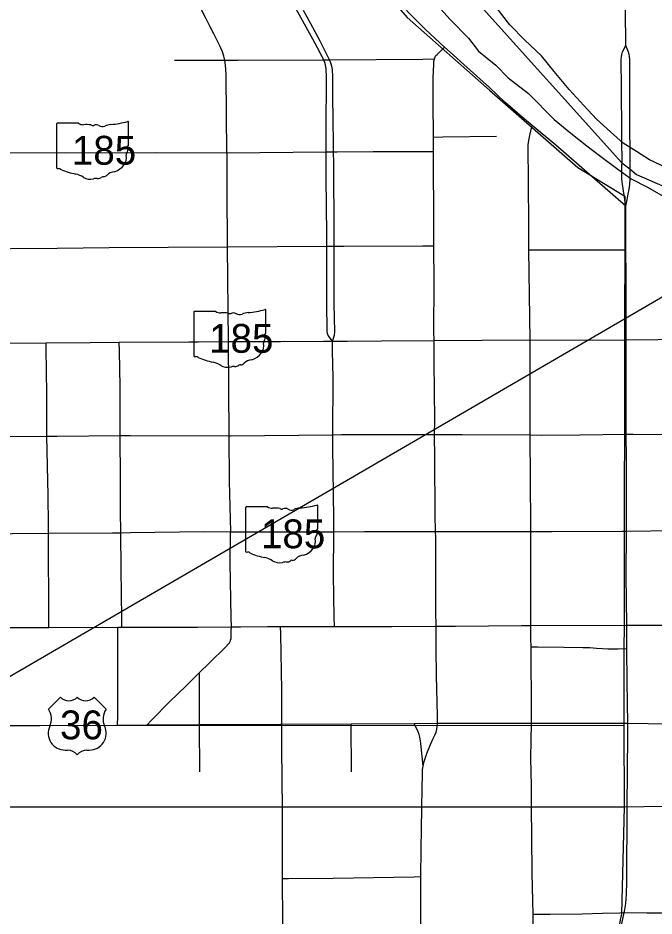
# Model space of a CAD drawing. Extents: x -87 to 2145, y -2128 to 440.
# Drawn here: x 517.5 to 594.3, y -979.3 to -870.9 of the extents above; entities that cross this region are included whole.
import ezdxf

# ---------------------------------------------------------------- set-up
doc = ezdxf.new("R2010")
doc.units = 0
for name, color, linetype in [('Default', 7, 'Continuous'), ('GM_X_City_Street', 7, 'Continuous'), ('GM_X_County_Road', 7, 'Continuous'), ('GM_X_Major_River', 7, 'Continuous'), ('GM_X_Rail_Line', 7, 'Continuous'), ('GM_X_State_Route', 7, 'Continuous'), ('GM_X_State_Shield', 7, 'Continuous'), ('GM_X_Township', 7, 'Continuous'), ('GM_X_Township_Text', 7, 'Continuous'), ('GM_X_US_Route', 7, 'Continuous'), ('GM_X_US_Shield', 7, 'Continuous'), ('SC_Scratch1', 7, 'Continuous')]:
    doc.layers.add(name, color=color, linetype=linetype)

msp = doc.modelspace()

# ---------------------------------------------------------------- linework, layer by layer
at = {"layer": 'Default'}
msp.add_circle((557.31, -928.35), 114.66, dxfattribs=at)
at = {"layer": 'GM_X_City_Street'}
msp.add_line((557.79, -961.89), (557.74, -956.06), dxfattribs=at)
for points in [[(555.49, -909.89), (554.97, -909.19), (554.89, -908.94), (554.86, -908.67), (554.85, -908.4), (554.81, -905.54), (554.82, -903.09), (554.82, -898.7), (554.82, -898.42), (554.82, -897.01), (554.75, -890.14), (554.75, -887.97), (554.75, -887.01), (554.74, -886.41), (554.75, -883.05), (554.79, -879.41), (554.79, -878.03), (554.74, -876.95), (554.67, -876.57), (554.6, -876.34), (554.46, -875.91), (554.35, -875.7), (554.21, -875.43), (554.11, -875.23), (553.7, -874.47), (553.14, -873.4), (550.86, -869.36)], [(542.73, -887.14), (542.68, -877.84), (542.64, -876.98), (542.54, -876.23), (542.49, -875.95), (542.4, -875.48), (542.21, -874.95), (541.9, -874.21), (541.55, -873.49), (541.18, -872.77), (540.73, -871.91), (540.25, -870.97), (539.65, -869.81)], [(555.49, -909.89), (555.66, -909.41), (555.74, -909.14), (555.78, -908.74), (555.71, -905.36), (555.71, -902.88), (555.69, -899.41), (555.69, -898.42), (555.7, -895.31), (555.65, -890.02), (555.65, -888.4), (555.64, -887), (555.64, -886.01), (555.56, -880.31), (555.56, -878.43), (555.55, -877.96), (555.5, -877.08), (555.43, -876.68), (555.35, -876.44), (555.27, -876.21), (555.13, -875.91), (554.98, -875.58), (554.01, -873.64), (553.15, -871.99), (552, -869.94)], [(566.31, -966.29), (566.31, -966.07), (566.36, -961.99), (566.38, -961.6), (566.44, -961.19), (566.56, -960.61), (566.88, -959.67), (567.32, -958.57), (567.61, -957.94), (567.88, -957.43), (568.02, -957.08), (568.11, -956.71), (568.2, -956.01), (568.17, -955.06), (568.06, -950.28), (568.03, -946.94), (568.01, -944.29), (567.99, -942.51), (567.99, -939.1), (567.97, -933.59), (567.96, -932.86), (567.92, -930.85), (567.87, -923.97), (567.83, -921.15), (567.85, -919.46), (567.77, -912.37), (567.76, -909.78), (567.75, -908.73), (567.76, -902.84), (567.75, -898.36), (567.74, -896.28), (567.71, -886.98), (567.7, -885.24), (567.67, -880.94), (567.67, -879.07), (567.65, -878.04), (567.68, -877.26), (567.72, -876.44), (567.75, -876.09), (567.81, -875.8), (567.9, -875.56), (568, -875.39), (568.13, -875.26), (569.03, -874.36)], [(536.44, -875.96), (542.49, -875.95), (544.11, -875.95), (554.46, -875.91), (554.84, -875.91), (555.13, -875.91)], [(555.13, -875.91), (566.4, -875.81), (567.81, -875.8)], [(579.36, -909.7), (579.21, -898.86), (579.21, -895.64), (579.14, -886.13), (579.25, -885.44), (579.36, -884.83), (579.61, -883.84)], [(567.7, -885.24), (568.84, -885.22), (575.32, -885.12)], [(542.73, -887.14), (554.75, -887.01), (555.64, -887), (556.08, -887), (560.4, -886.98), (566.46, -886.98), (567.71, -886.98)], [(447.52, -899), (448.88, -898.99), (463.39, -898.9), (473.66, -898.82), (474.44, -898.82), (485.35, -898.8), (487.31, -898.8), (495.53, -898.78), (499.39, -898.77), (502.67, -898.76), (509.93, -898.74), (510.42, -898.73), (510.99, -898.73), (522.28, -898.66), (528.55, -898.57), (542.79, -898.48), (554.82, -898.42), (555.69, -898.42), (556.86, -898.41), (566.4, -898.36), (567.75, -898.36)], [(579.21, -898.86), (580.2, -898.86), (590.94, -898.83)], [(511.1, -910.15), (520.94, -910.07), (526.26, -910.03), (529.75, -910.01), (538.14, -909.95), (539.31, -909.95), (542.91, -909.93), (549.23, -909.9), (554.42, -909.89), (555.49, -909.89), (557.26, -909.88), (561.42, -909.83), (567.76, -909.78), (579.36, -909.7)], [(521.27, -944.43), (521.26, -943.73), (521.25, -939.89), (521.21, -936.85), (521.21, -934.23), (521.2, -933.07), (521.2, -932.04), (521.17, -928.51), (521.03, -921.34), (521.01, -916.24), (520.95, -910.75), (520.94, -910.07)], [(530.09, -944.42), (530.07, -943.35), (529.97, -937.41), (529.93, -933), (529.91, -930.37), (529.9, -926.55), (529.87, -921.26), (529.87, -918.51), (529.85, -915.37), (529.77, -911.1), (529.75, -910.01)], [(555.75, -944.34), (555.72, -943.19), (555.63, -938.09), (555.67, -932.88), (555.68, -931.29), (555.58, -925.45), (555.55, -922.76), (555.56, -921.17), (555.6, -914.3), (555.52, -911.06), (555.49, -909.89)], [(516.04, -921.4), (521.03, -921.34), (522.25, -921.33), (529.87, -921.26), (531.06, -921.25), (543, -921.32), (543.17, -921.32), (555.56, -921.17), (556.6, -921.16), (565.89, -921.14), (567.83, -921.15), (571.15, -921.16), (579.39, -921.2), (580.78, -921.21), (585.38, -921.17), (590.98, -921.1)], [(590.98, -921.1), (591.8, -921.1), (600.28, -921.13), (602.53, -921.13), (605.79, -921.13), (611.39, -921.09), (613.63, -921.08), (618.78, -921.04), (621.83, -921.02), (624.61, -921.01), (628.82, -920.99), (632.37, -920.97), (645.04, -920.93), (650.18, -920.91), (652.92, -920.95), (653.24, -920.99), (653.4, -921.07), (653.59, -921.27)], [(477.26, -933.33), (480.47, -933.36), (485.87, -933.31), (488.48, -933.29), (493.15, -933.26), (497.97, -933.23), (499.69, -933.22), (507.01, -933.18), (510.79, -933.16), (511.94, -933.15), (516.84, -933.08), (521.2, -933.07), (528.93, -933), (529.93, -933), (531.1, -932.99), (539.96, -932.86), (543.17, -932.88)], [(543.3, -944.37), (543.28, -943.28), (543.15, -936.6), (543.17, -932.88)], [(529.56, -956.24), (529.57, -955.14), (529.59, -949.57), (529.6, -945.36), (529.6, -944.42)], [(533.11, -956.22), (533.66, -955.65), (535.86, -953.37), (537.79, -951.55), (539.43, -949.9), (540.64, -948.7), (542.62, -946.79), (542.95, -946.44), (543.06, -946.28), (543.16, -946.14), (543.21, -945.96), (543.27, -945.78), (543.28, -945.59), (543.29, -945.39), (543.29, -944.81), (543.3, -944.37)], [(549.45, -966.4), (549.45, -966.08), (549.41, -963.06), (549.4, -958.72), (549.38, -956.12), (549.37, -955.44), (549.38, -952.02), (549.26, -945.24), (549.24, -944.34)], [(591.03, -944.16), (592.27, -944.16), (602.6, -944.17), (613.95, -944.18)], [(579.48, -946.77), (580.29, -946.78), (583.42, -946.81), (585.71, -946.88), (586.57, -946.88), (587.38, -946.93), (588.09, -946.99), (588.74, -947.04), (590.01, -947.02), (591.06, -947)], [(539.49, -961.87), (539.46, -956.18), (539.44, -950.8), (539.43, -949.9)], [(566.44, -961.19), (566.17, -958.45), (566.14, -958.13), (566.06, -957.7), (565.95, -957.37), (565.84, -957.06), (565.37, -956.02)], [(579.54, -966.23), (579.52, -963.59), (579.47, -960.2), (579.55, -955.99)], [(549.53, -981.56), (549.51, -978.93), (549.48, -975.8), (549.48, -974.74), (549.48, -971.19), (549.45, -966.4)], [(566.19, -981.56), (566.17, -978.14), (566.19, -974.72), (566.19, -974.53), (566.21, -971.22), (566.31, -966.29)], [(580.14, -1040.72), (580.1, -1034.93), (580.07, -1031.28), (580.06, -1027.75), (580.07, -1025.68), (580.03, -1022.33), (580.01, -1017.58), (579.99, -1013.97), (579.95, -1010.78), (579.93, -1009.25), (579.87, -1003.73), (579.86, -1002.66), (579.86, -999.61), (579.83, -995.18), (579.79, -992.85), (579.79, -992.42), (579.8, -990.56), (579.81, -988.68), (579.79, -981.6), (579.73, -979.06), (579.7, -977.47), (579.63, -974.1), (579.57, -969.74), (579.54, -966.23)], [(549.48, -974.74), (550.18, -974.74), (555.6, -974.71), (565.36, -974.54), (566.19, -974.53)], [(579.73, -979.06), (580.89, -979.06), (581.78, -979.06), (585.63, -979.01), (588.09, -978.95), (590.2, -978.89), (590.72, -978.87)]]:
    msp.add_lwpolyline(points, dxfattribs=at)
at = {"layer": 'GM_X_County_Road'}
for p, q in [((590.46, -888.42), (590.44, -885.42)), ((590.94, -895.97), (590.93, -893.58)), ((590.94, -898.83), (590.94, -895.97)), ((542.79, -898.48), (542.91, -909.93)), ((579.36, -909.7), (590.96, -909.74)), ((590.98, -921.1), (590.96, -909.74)), ((542.91, -909.93), (543, -921.32)), ((590.99, -932.82), (602.56, -932.66)), ((521.27, -944.43), (529.6, -944.42)), ((529.6, -944.42), (530.09, -944.42)), ((549.24, -944.34), (555.75, -944.34)), ((579.46, -944.2), (591.03, -944.16)), ((591.06, -947), (591.03, -944.16))]:
    msp.add_line(p, q, dxfattribs=at)
for points in [[(590.92, -874.19), (590.84, -865.55), (590.8, -860.46), (590.8, -857.59), (590.94, -854.99)], [(590.44, -885.42), (590.44, -884.69), (590.39, -879.3), (590.37, -875.87), (590.39, -875.55), (590.43, -875.27), (590.51, -874.96), (590.92, -874.19)], [(591.42, -884.83), (591.41, -883.41), (591.4, -877.03), (591.41, -875.86), (591.38, -875.52), (591.32, -875.25), (591.24, -874.98), (590.92, -874.19)], [(591.46, -889.15), (591.44, -886.25), (591.42, -884.83)], [(515.97, -887.11), (523.32, -887.12), (534.26, -887.08), (542.73, -887.14)], [(542.73, -887.14), (542.75, -891.67), (542.79, -898.48)], [(590.45, -890.27), (590.43, -889.94), (590.44, -889.65), (590.45, -888.54), (590.46, -888.42)], [(590.93, -893.58), (591.36, -891.32), (591.46, -890.38), (591.46, -889.15)], [(590.93, -893.58), (590.5, -890.93), (590.45, -890.27)], [(590.96, -909.74), (590.95, -901.97), (590.94, -898.83)], [(579.39, -921.2), (579.39, -921.08), (579.36, -914.55), (579.36, -909.7)], [(543, -921.32), (543.04, -926.8), (543.17, -932.88)], [(579.45, -932.84), (579.46, -932.11), (579.39, -921.2)], [(590.99, -932.82), (590.99, -930.44), (590.99, -924.12), (590.98, -921.1)], [(543.17, -932.88), (549.93, -932.89), (555.67, -932.88)], [(555.67, -932.88), (559.36, -932.87), (567.96, -932.86)], [(567.96, -932.86), (568.98, -932.86), (579.45, -932.84)], [(579.45, -932.84), (582.01, -932.84), (590.49, -932.82), (590.99, -932.82)], [(579.46, -944.2), (579.45, -943.28), (579.45, -932.84)], [(591.03, -944.16), (590.97, -938.16), (590.99, -932.82)], [(510.86, -944.46), (518.72, -944.43), (521.27, -944.43)], [(530.09, -944.42), (535.39, -944.42), (539.22, -944.39), (543.3, -944.37)], [(543.3, -944.37), (544.41, -944.36), (547.64, -944.34), (549.24, -944.34)], [(555.75, -944.34), (557.15, -944.34), (559.61, -944.34), (562.66, -944.33), (568.01, -944.29)], [(568.01, -944.29), (570.37, -944.27), (578.31, -944.21), (579.46, -944.2)], [(579.48, -946.77), (579.47, -945.83), (579.46, -944.2)], [(579.55, -955.99), (579.54, -954.84), (579.48, -946.77)], [(591.15, -955.99), (591.1, -951.04), (591.06, -947)], [(591.09, -966.16), (591.16, -957.42), (591.15, -955.99)], [(590.72, -978.87), (590.75, -978.75), (590.91, -977.76), (591, -976.66), (591.04, -975.18), (591.09, -966.16)], [(589.21, -990.44), (589.2, -990.23), (589.25, -988.67), (589.45, -986.26), (589.58, -985.01), (590.01, -982.22), (590.19, -981.45), (590.37, -980.61), (590.72, -978.87)], [(590.72, -978.87), (593.47, -978.89), (595.33, -978.91)]]:
    msp.add_lwpolyline(points, dxfattribs=at)
at = {"layer": 'GM_X_Major_River'}
for points in [[(567.86, -868.99), (569.7, -871.05), (571.91, -873.3), (573.15, -874.87), (575.24, -876.57), (576.73, -878.09), (579.17, -879.98), (582.27, -883.13), (584.3, -884.78), (586.21, -886.3), (587.76, -887.46), (589.97, -889.1), (591.58, -890.26), (593.55, -891.3), (595.71, -892.52)], [(595.75, -888.92), (593.77, -888), (592.22, -886.96), (590.6, -885.98), (589.05, -884.59), (587.39, -883.07), (585.84, -881.43), (584.06, -879.49), (582.27, -877.31), (580.73, -875.43), (578.71, -873.55), (576.92, -871.67), (575.26, -869.55)]]:
    msp.add_lwpolyline(points, dxfattribs=at)
at = {"layer": 'GM_X_Rail_Line'}
for p in [(590.66, -956.29), (510.36, -966.08)]:
    msp.add_line(p, (590.7, -966.1), dxfattribs=at)
for points in [[(522.94, -818.96), (529.06, -828.87), (539.31, -836.89), (547.13, -850.77), (564.54, -870.78), (574.48, -879.59), (585.14, -888.91), (590.8, -892.38), (590.66, -956.29)], [(510.36, -966.08), (510.5, -956.23), (590.66, -956.29)], [(590.7, -966.1), (590.41, -979), (589.08, -985.35), (588.87, -992.45), (592.89, -1037.35)], [(590.7, -966.1), (621.35, -965.58), (637.65, -966.57), (649.78, -967.71), (660.3, -969.52), (664.01, -970.34)]]:
    msp.add_lwpolyline(points, dxfattribs=at)
at = {"layer": 'GM_X_State_Route'}
for p, q in [((590.94, -895.97), (590.93, -893.58)), ((590.94, -898.83), (590.94, -895.97))]:
    msp.add_line(p, q, dxfattribs=at)
for points in [[(566.73, -872.25), (566.24, -871.77), (565.75, -871.29), (564.96, -870.46), (564.05, -869.52), (561.58, -866.71), (560.17, -865.07), (558.86, -863.6), (556.81, -861.22), (555.15, -859.26), (553.42, -857.29), (550.27, -853.64), (546.65, -849.49), (544.92, -847.47), (543.1, -845.39)], [(590.93, -893.58), (582.48, -886.23), (579.61, -883.84), (578.7, -883.08), (576.33, -881.01), (574.46, -879.26), (571.75, -876.83), (569.7, -874.98), (569.03, -874.36), (566.73, -872.25)], [(590.96, -909.74), (590.95, -901.97), (590.94, -898.83)], [(602.47, -909.79), (602.47, -909.63), (590.96, -909.74)]]:
    msp.add_lwpolyline(points, dxfattribs=at)
at = {"layer": 'GM_X_State_Shield'}
for p, q in [((522.19, -883.66), (522.19, -888.95)), ((524.82, -883.57), (522.28, -883.57)), ((530.89, -886.2), (530.89, -883.44)), ((530.89, -886.2), (530.89, -886.2)), ((538.77, -906.37), (538.77, -911.65)), ((541.4, -906.28), (538.85, -906.28)), ((547.47, -908.91), (547.47, -906.15)), ((547.47, -908.91), (547.47, -908.91)), ((545.02, -929.97), (545.02, -935.25)), ((547.66, -929.88), (545.11, -929.88)), ((553.72, -932.51), (553.72, -929.75)), ((553.72, -932.51), (553.72, -932.51))]:
    msp.add_line(p, q, dxfattribs=at)
for centre, major_axis, start_param, end_param in [((522.29, -883.65), (0.101, 0), 1.712693, 3.28349), ((525.43, -882.96), (0.978, 0), 4.042523, 4.731795), ((525.76, -886.54), (3.51, 0), 1.404758, 1.657858), ((528.97, -885.19), (1.86, 0), 1.699011, 2.107814), ((527.79, -876.37), (9.23, 0), 4.814394, 5.042369), ((530.8, -883.43), (0.0969, 0), 6.141152, 7.989035), ((526.55, -883.62), (0.282, 0), 3.836095, 5.185415), ((526.97, -884.23), (0.586, 0), 0.950623, 2.079405), ((527.72, -883.4), (0.705, 0), 4.081561, 5.145723), ((530.87, -886.41), (0.15, 0), 1.883978, 3.671073), ((529.92, -886.76), (0.9, 0), 5.934695, 6.695948), ((530.79, -886.22), (0.104, 0), 5.05454, 6.418171), ((528.31, -887.71), (2.31, 0), 5.101752, 6.440018), ((531.24, -887.36), (0.655, 0), 2.387724, 3.262537), ((522.29, -888.96), (0.102, 0), 3.00124, 4.508301), ((522.31, -888.42), (0.776, 0), 4.665946, 4.897461), ((522.47, -889.25), (0.28, 0), 0.519207, 1.627899), ((526, -884.5), (6.66, 0), 4.195997, 4.488961), ((524.01, -891.32), (2.08, 0), 0.823519, 1.323587), ((526.27, -889.28), (1.32, 0), 4.026481, 4.996735), ((527.03, -891.1), (1.09, 0), 1.495662, 1.94098), ((527.13, -889.67), (0.705, 0), 4.691044, 5.507374), ((527.77, -890.18), (0.198, 0), 1.147584, 2.315152), ((527.68, -889.46), (0.746, 0), 4.937069, 5.64225), ((529.28, -890.43), (1.26, 0), 1.647645, 2.488434), ((538.87, -906.36), (0.101, 0), 1.712693, 3.28349), ((542.01, -905.67), (0.978, 0), 4.042523, 4.731795), ((542.33, -909.25), (3.51, 0), 1.404758, 1.657858), ((543.13, -906.33), (0.282, 0), 3.836095, 5.185415), ((543.54, -906.94), (0.586, 0), 0.950623, 2.079405), ((545.55, -907.89), (1.86, 0), 1.699011, 2.107814), ((544.37, -899.08), (9.23, 0), 4.814394, 5.042369), ((547.37, -906.14), (0.0969, 0), 6.141152, 7.989035), ((544.3, -906.1), (0.705, 0), 4.081561, 5.145723), ((547.82, -910.07), (0.655, 0), 2.387724, 3.262537), ((547.45, -909.12), (0.15, 0), 1.883978, 3.671073), ((546.49, -909.46), (0.9, 0), 5.934695, 6.695948), ((547.36, -908.92), (0.104, 0), 5.05454, 6.418171), ((544.89, -910.42), (2.31, 0), 5.101752, 6.440018), ((538.87, -911.67), (0.102, 0), 3.00124, 4.508301), ((538.88, -911.12), (0.776, 0), 4.665946, 4.897461), ((539.04, -911.96), (0.28, 0), 0.519207, 1.627899), ((542.57, -907.21), (6.66, 0), 4.195997, 4.488961), ((540.59, -914.03), (2.08, 0), 0.823519, 1.323587), ((542.84, -911.98), (1.32, 0), 4.026481, 4.996735), ((543.61, -913.81), (1.09, 0), 1.495662, 1.94098), ((543.7, -912.38), (0.705, 0), 4.691044, 5.507374), ((544.34, -912.89), (0.198, 0), 1.147584, 2.315152), ((544.26, -912.17), (0.746, 0), 4.937069, 5.64225), ((545.86, -913.14), (1.26, 0), 1.647645, 2.488434), ((545.12, -929.96), (0.101, 0), 1.712693, 3.28349), ((548.26, -929.27), (0.978, 0), 4.042523, 4.731795), ((548.59, -932.85), (3.51, 0), 1.404758, 1.657858), ((549.38, -929.93), (0.282, 0), 3.836095, 5.185415), ((549.8, -930.54), (0.586, 0), 0.950623, 2.079405), ((550.56, -929.71), (0.705, 0), 4.081561, 5.145723), ((551.8, -931.49), (1.86, 0), 1.699011, 2.107814), ((550.62, -922.68), (9.23, 0), 4.814394, 5.042369), ((553.63, -929.74), (0.0969, 0), 6.141152, 7.989035), ((553.62, -932.52), (0.104, 0), 5.05454, 6.418171), ((554.07, -933.67), (0.655, 0), 2.387724, 3.262537), ((553.7, -932.72), (0.15, 0), 1.883978, 3.671073), ((552.75, -933.06), (0.9, 0), 5.934695, 6.695948), ((551.14, -934.02), (2.31, 0), 5.101752, 6.440018), ((545.12, -935.27), (0.102, 0), 3.00124, 4.508301), ((545.14, -934.72), (0.776, 0), 4.665946, 4.897461), ((545.3, -935.56), (0.28, 0), 0.519207, 1.627899), ((548.83, -930.81), (6.66, 0), 4.195997, 4.488961), ((552.11, -936.74), (1.26, 0), 1.647645, 2.488434), ((546.84, -937.63), (2.08, 0), 0.823519, 1.323587), ((549.1, -935.58), (1.32, 0), 4.026481, 4.996735), ((549.86, -937.41), (1.09, 0), 1.495662, 1.94098), ((549.96, -935.98), (0.705, 0), 4.691044, 5.507374), ((550.6, -936.49), (0.198, 0), 1.147584, 2.315152), ((550.51, -935.77), (0.746, 0), 4.937069, 5.64225)]:
    msp.add_ellipse(centre, major_axis=major_axis, ratio=0.8, start_param=start_param, end_param=end_param, dxfattribs=at)
at = {"layer": 'GM_X_Township'}
msp.add_lwpolyline([(548.97, -813.99), (549.6, -816.47), (550.13, -825.76), (551.52, -838.23), (552.78, -845.01), (563.65, -859.09), (572.1, -868), (572.6, -868.5), (590.42, -888.34), (591.42, -889.07), (592.21, -889.76), (608.29, -896.75), (620.89, -899.92), (626.55, -900.24), (637.78, -902.82), (650.07, -906.54), (658.06, -908.29), (662.2, -909.77), (666.21, -911.67), (668.3, -912.41), (671.07, -913.98)], dxfattribs=at)
at = {"layer": 'GM_X_Township_Text'}
msp.add_lwpolyline([(548.97, -813.99), (549.6, -816.47), (550.13, -825.76), (551.52, -838.23), (552.78, -845.01), (563.65, -859.09), (572.1, -868), (572.6, -868.5), (590.42, -888.34), (591.42, -889.07), (592.21, -889.76), (608.29, -896.75), (620.89, -899.92), (626.55, -900.24), (637.78, -902.82), (650.07, -906.54), (658.06, -908.29), (662.2, -909.77), (666.21, -911.67), (668.3, -912.41), (671.07, -913.98)], dxfattribs=at)
at = {"layer": 'GM_X_US_Route'}
for points in [[(510.8, -956.34), (529.56, -956.24), (533.11, -956.22), (539.46, -956.18), (549.23, -956.12), (549.38, -956.12), (557.74, -956.06), (565.37, -956.02), (568.2, -956.01), (569.92, -956)], [(569.92, -956), (570.71, -956), (579.55, -955.99)], [(579.55, -955.99), (590.26, -955.99), (591.15, -955.99)], [(591.15, -955.99), (598.49, -956.1), (602.67, -956.1), (602.66, -955.46)]]:
    msp.add_lwpolyline(points, dxfattribs=at)
at = {"layer": 'GM_X_US_Shield'}
for p, q in [((522.65, -952.87), (521.2, -954.32)), ((528.16, -954.32), (526.71, -952.87)), ((523.23, -959.25), (523.52, -959.25)), ((525.84, -959.25), (526.13, -959.25))]:
    msp.add_line(p, q, dxfattribs=at)
for centre, radius, start, end in [((523.67, -951.84), 1.45, 225.573, 314.427), ((525.7, -951.84), 1.45, 225.573, 314.427), ((519.54, -955.49), 2.03, 334.5471, 35.0009), ((529.83, -955.49), 2.03, 144.9991, 205.4529), ((523.21, -957.22), 2.03, 154.8319, 270.6383), ((526.16, -957.22), 2.03, 269.3617, 25.1681), ((523.52, -960.7), 1.45, 36.8699, 90), ((525.84, -960.7), 1.45, 90, 143.1301)]:
    msp.add_arc(centre, radius, start, end, dxfattribs=at)
at = {"layer": 'SC_Scratch1'}
msp.add_line((902.07, -726.16), (-86.99, -1301.38), dxfattribs=at)

# ---------------------------------------------------------------- texts
at = {"layer": 'GM_X_State_Shield'}
for p in [(524.04, -888.57), (540.61, -911.28), (546.87, -934.88)]:
    msp.add_text('185', height=3.48, dxfattribs=at).set_placement(p)
at = {"layer": 'GM_X_US_Shield'}
msp.add_text('36', height=3.48, dxfattribs=at).set_placement((522.61, -957.95))

doc.saveas('drawing.dxf')
